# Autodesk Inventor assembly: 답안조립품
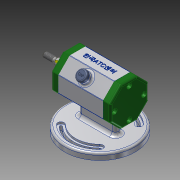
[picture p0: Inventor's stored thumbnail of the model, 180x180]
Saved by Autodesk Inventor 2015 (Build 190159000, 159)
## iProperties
Created: 2017-06
Part Number: 답안조립품
Document SubType Name: Assembly
Designer: user
Author: user
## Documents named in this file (10)
- C:\Users\user\Desktop\470607V1001\답안조립품.iam
- C:\Users\user\Desktop\470607V1001\본체.ipt
- C:\Users\user\Desktop\470607V1001\고무캡.ipt
- C:\Users\user\Desktop\470607V1001\축.ipt
- C:\Users\user\Desktop\470607V1001\베어링 15 x 32 x 9.ipt
- C:\Users\user\Desktop\470607V1001\뒤커버.ipt
- C:\Users\user\Desktop\470607V1001\앞커버.ipt
- C:\Users\user\Desktop\470607V1001\오일 실 15 25 7.ipt
- C:\Users\user\Desktop\470607V1001\키 3 x 3 x 12.ipt
- C:\Users\user\Desktop\470607V1001\볼트 M4 x 12.ipt
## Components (1 placed, 1 different names)
1. 고무캡:1 — 각도:1
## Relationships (1: Angle 1)
- 각도:1 [Angle]: 고무캡:1
